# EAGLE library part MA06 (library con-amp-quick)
AMP QUICK CONNECTOR
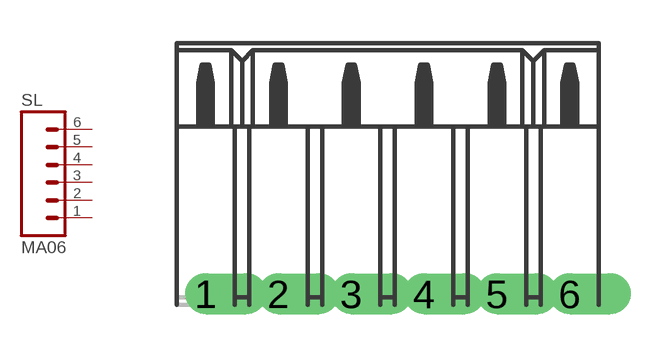
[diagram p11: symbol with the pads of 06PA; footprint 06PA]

Designator prefix SL

## MA06  [06PA]
1  1  pas
2  2  pas
3  3  pas
4  4  pas
5  5  pas
6  6  pas

## Footprint 06PA (pad centres in mm)
AMP QUICK CONNECTOR
drill 0.914 offset: 1 -6.35,0; 2 -3.81,0; 3 -1.27,0; 4 1.27,0; 5 3.81,0; 6 6.35,0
